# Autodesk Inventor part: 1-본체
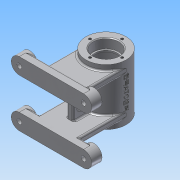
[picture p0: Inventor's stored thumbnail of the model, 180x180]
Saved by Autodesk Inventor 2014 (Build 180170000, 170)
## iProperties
Created: 2015-11
Part Number: 1-본체
Material: 알루미늄 6061
Document SubType Name: Modeling
Designer: 27
Density: 2.71 g/cm^3
Appearance: 알루미늄 - 평지
Mass: 359.021 g
Surface Area: 460.312 cm^2
Volume: 132.48 cm^3
Author: 27
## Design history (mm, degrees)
sketch "스케치1"
  geometry: C1 r 25 at (0, 0); 1 further point
  constraints: 1 centre point, 1 coincident
  dimensions: "d0" = 50 diameter of C1
extrude "돌출1" new body sketch "스케치1" distance "d1" = 70; taper "d2" = 0 deg
node "작업 평면1"
sketch "스케치2"
  geometry: L1 (25, 70)-(-25, 70) reference; L2 (-25, 0)-(25, 0) reference; L3 (-25, 0)-(-25, 70) reference; L4 (25, 0)-(25, 70) reference; L5 (-40, 75)-(40, 75); L6 (-40, 55)-(40, 55); A1 r 10 centre (-40, 65) between (-40, 75) and (-40, 55); A2 r 10 centre (40, 65) between (40, 55) and (40, 75); 7 further points
  constraints: 5 end point, 4 midpoint, 4 point on circle, 3 vertical alignment, 2 centre point, 2 horizontal alignment, 2 tangent, 1 parallel, 1 perpendicular
  dimensions: "d4" = 20 diameter of A1; "d5" = 20 diameter of A2; "d6" = 80 distance of A2.centre A1.centre; "d9" = 40 distance from line of L5 point (0, 35)
extrude "돌출2" join sketch "스케치2" distance "d10" = 10; taper "d11" = 0 deg
sketch "스케치3"
  geometry: C1 r 10 at (-40, -65); C2 r 10 at (40, -65); A1 r 10 centre (40, -65) between (40, -75) and (40, -55) reference; A2 r 10 centre (-40, -65) between (-40, -55) and (-40, -75) reference; 1 further point
  constraints: 2 centre point, 2 coincident, 1 concentric
  dimensions: "d12" = 20 diameter of C1
extrude "돌출3" join sketch "스케치3" distance "d13" = 3; taper "d14" = 0 deg
node "작업 평면3"
  node "작업 평면2"
sketch "스케치4"
  geometry: L1 (80, 0)-(0, 0) reference; L2 (0, 0)-(0, 10) reference; L3 (80, 10)-(0, 10) reference; L4 (80, 0)-(80, 10) reference; L5 (15, 68)-(15, 10); L6 (65, 68)-(65, 10); L7 (15, 10)-(65, 10); L8 (15, 68)-(65, 68); A1 r 25 centre (40, 68) between (15, 68) and (65, 68) reference; 1 further point
  constraints: 8 end point, 2 parallel, 2 perpendicular, 2 point on circle, 2 point on line, 2 tangent
extrude "돌출4" join sketch "스케치4" distance "d16" = 8; taper "d17" = 0 deg
node "작업 평면4"
node "작업 평면6"
sketch "스케치5"
  geometry: L1 (-25, 0)-(-25, 70) reference; L2 (-58, 55)-(0, 55) reference; L3 (-58, 15)-(0, 15) reference; L4 (-45, 57.054)-(-45, 11.993); L5 (-45, 57.054)-(-19.914, 57.054); L6 (-19.914, 57.054)-(-19.914, 11.993); L7 (-19.914, 11.993)-(-45, 11.993); 1 further point
  constraints: 8 end point, 3 perpendicular, 1 parallel
  dimensions: "d19" = 20 distance between parallel lines of L4 L1; "d22" = 5.08556 distance between parallel lines of L1 L6; "d23" = 3.00724 distance between parallel lines of L7 L3; "d24" = 2.05433 distance between parallel lines of L2 L5
extrude "돌출5" join sketch "스케치5" stored distance "d25" = 8; taper "d26" = 0 deg
node "작업 평면8"
sketch "스케치7"
  geometry: L1 (25, 0)-(25, 70) reference; L2 (-25, 0)-(-25, 70) reference; L3 (-25, 0)-(25, 0) reference; L4 (25, 70)-(-25, 70) reference; C1 r 5 at (0, 35); 3 further points
  constraints: 2 midpoint, 1 centre point, 1 horizontal alignment, 1 vertical alignment
  dimensions: "d29" = 10 diameter of C1
extrude "돌출6" join sketch "스케치7" stored distance "d30" = 8; taper "d31" = 0 deg
sketch "스케치8"
  geometry: L1 (15, -24.678)-(55, -24.678) reference; L2 (55, -24.678)-(55, -45) reference; L3 (27, -31.5)-(43, -31.5); L4 (43, -38.5)-(27, -38.5); L5 (-5, -68)-(15, -68) reference; A1 r 3.5 centre (43, -35) between (43, -38.5) and (43, -31.5); A2 r 3.5 centre (27, -35) between (27, -31.5) and (27, -38.5); 3 further points
  constraints: 4 end point, 4 point on circle, 4 tangent, 2 centre point, 2 midpoint, 1 parallel, 1 perpendicular, 1 vertical alignment
  dimensions: "d32" = 23 dimension on A1 A2; "d33" = 3.5 radius of A1; "d34" = 33 distance from line of A2.centre L5
extrude "돌출7" cut sketch "스케치8" stored distance "d35" = 8; taper "d36" = 0 deg
hole "구멍1" diameter "d39" = 28; stored, may be unused: countersink angle "d43" = 90 deg, drill point angle "d45" = 0 deg; dims "d40" = 6, "d41" = 32, "d42" = 12, "d44" = 14, "d59" = 10, "d60" = 10
hole "구멍2" diameter "d48" = 28; stored, may be unused: countersink angle "d52" = 90 deg, drill point angle "d54" = 0 deg; dims "d49" = 6, "d50" = 32, "d51" = 12, "d53" = 14, "d61" = 10, "d62" = 10
node "작업 평면9"
sketch "스케치10"
  geometry: C1 r 14 at (0, 0) reference; 1 further point
  constraints: 1 coincident
hole "구멍3" sketch "스케치10" at (0, 0) diameter "d57" = 42; stored, may be unused: countersink angle "d65" = 90 deg, drill point angle "d67" = 0 deg; dims "d58" = 6, "d63" = 32, "d64" = 12, "d66" = 42
node "작업 평면10"
sketch "스케치11"
  geometry: L1 (0, 0)-(14, -24.249); A1 r 25 centre (0, 0) between (-25, 0) and (-4, -24.678) reference; A2 r 25 centre (0, 0) between (4, -24.678) and (25, 0) reference; A3 r 25 centre (0, 0) between (-25, 0) and (25, 0) reference; 1 further point
  constraints: 2 end point, 1 point on circle
  dimensions: "d68" = 30 deg dimension on L1.start point (0, -25) L1.end; "d69" = 28 distance of L1.start L1.end
node "작업 평면11"
sketch "스케치12"
  geometry: C1 r 6 at (0, 0); 2 further points
  constraints: 1 centre point, 1 coincident
  dimensions: "d70" = 12 diameter of C1
extrude "돌출8" join sketch "스케치12" stored distance "d71" = 8; taper "d72" = 0 deg
hole "구멍4" diameter "d75" = 5.188; stored, may be unused: countersink angle "d79" = 90 deg, drill point angle "d81" = 0 deg; dims "d73" = 10, "d74" = 10, "d76" = 6, "d77" = 32, "d78" = 12, "d80" = 42
hole "구멍5" diameter "d84" = 5.188; stored, may be unused: countersink angle "d88" = 90 deg, drill point angle "d90" = 0 deg; dims "d82" = 10, "d83" = 10, "d85" = 6, "d86" = 32, "d87" = 12, "d89" = 42
sketch "스케치13"
  geometry: C1 r 16 at (0, 0) reference; C2 r 25 at (0, 0) reference; A1 r 20 centre (0, 0) between (0, 20) and (0, -20); 2 further points
  constraints: 4 point on circle, 2 horizontal alignment, 2 vertical alignment, 1 centre point, 1 coincident
  dimensions: "d91" = 40 diameter of A1
hole "구멍6" sketch "스케치13" at (0, 20), (0, -20), (-20, 0), (20, 0) diameter "d92" = 3.242; stored, may be unused: countersink angle "d96" = 90 deg, drill point angle "d98" = 118 deg; dims "d93" = 8, "d94" = 32, "d95" = 12, "d97" = 10
node "작업 평면12"
node "작업 평면13"
sketch "스케치14"
  geometry: L1 (25, 0)-(25, 70) reference; L2 (25, 70)-(-25, 70) reference; L3 (-25, 0)-(25, 0) reference; L4 (-24.678, 55)-(-24.678, 15) reference; 2 further points
  constraints: 1 other
  dimensions: "d100" = 25 distance from line of point (0, 35) L1; "d101" = 35 distance from line of L2 point (0, 35)
feature "엠보싱1" sketch "스케치14" dims "d4" = 20, "d5" = 20, "d6" = 80, "d9" = 40, "d102" = 0.5, "d103" = 0
sketch "스케치15"
  geometry: C1 r 10 at (0, 0) reference; 1 further point
hole "구멍7" diameter "d106" = 6; stored, may be unused: countersink angle "d110" = 90 deg, drill point angle "d112" = 0 deg; dims "d104" = 10, "d105" = 10, "d107" = 8, "d108" = 12, "d109" = 4, "d111" = 10
hole "구멍8" diameter "d115" = 6; stored, may be unused: countersink angle "d119" = 90 deg, drill point angle "d121" = 0 deg; dims "d113" = 10, "d114" = 10, "d116" = 8, "d117" = 12, "d118" = 4, "d120" = 10
hole "구멍9" diameter "d124" = 6; stored, may be unused: countersink angle "d128" = 90 deg, drill point angle "d130" = 0 deg; dims "d122" = 10, "d123" = 10, "d125" = 8, "d126" = 12, "d127" = 4, "d129" = 10
hole "구멍10" diameter "d133" = 6; stored, may be unused: countersink angle "d137" = 90 deg, drill point angle "d139" = 0 deg; dims "d131" = 10, "d132" = 10, "d134" = 8, "d135" = 12, "d136" = 4, "d138" = 10
fillet "모깎기1" dims "d140" = 2
fillet "모깎기2" dims "d141" = 2
fillet "모깎기3" dims "d142" = 2
fillet "모깎기4" dims "d143" = 2
fillet "모깎기5" dims "d144" = 2
chamfer "모따기1" distance "d145" = 1; stored, may be unused: second distance "d146" = 2, angle "d147" = 45 deg
fillet "모깎기6" dims "d148" = 0.3
fillet "모깎기7" dims "d149" = 3
fillet "모깎기8" dims "d150" = 0.3
fillet "모깎기9" dims "d151" = 2
node "솔리드1"
mirror "대칭1"
mirror "대칭2"
mirror "대칭3"
node "투영된 루프1"
node "투영된 루프2"
node "투영된 루프3"
node "작업 평면5"
other parameters: "d3" = -68, "d18" = 0, "d28" = 28, "d99" = 26
